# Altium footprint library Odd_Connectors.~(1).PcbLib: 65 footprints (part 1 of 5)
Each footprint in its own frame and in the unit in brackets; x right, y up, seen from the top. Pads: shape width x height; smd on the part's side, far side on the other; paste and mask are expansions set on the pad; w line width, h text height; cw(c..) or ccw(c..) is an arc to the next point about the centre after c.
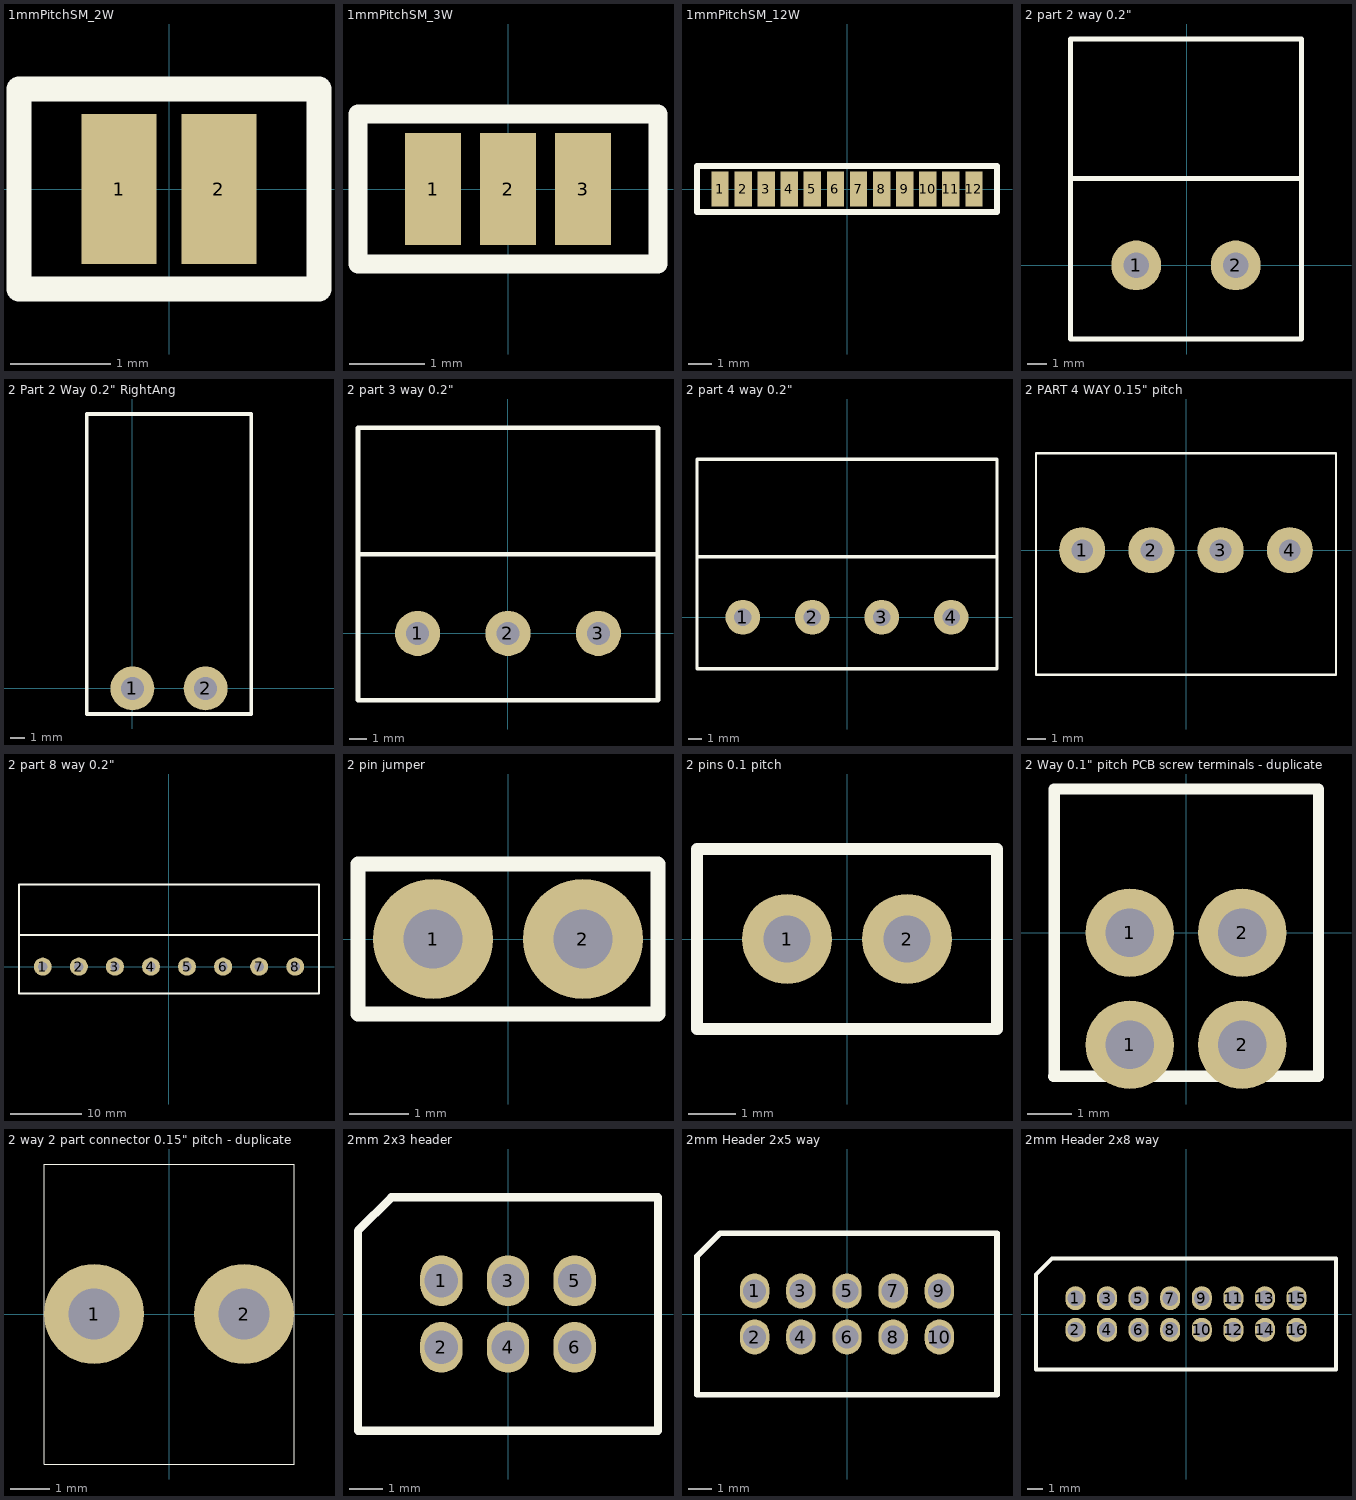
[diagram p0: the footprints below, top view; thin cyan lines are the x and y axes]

## 1mmPitchSM_2W [mm]
pads (2):
  rect 0.75x1.5 smd: 1(-0.5,0) 2(0.5,0)
Top Overlay:
  lines w0.254: -1.5,-1 -1.5,1 1.5,1 1.5,-1 -1.5,-1

## 1mmPitchSM_3W [mm]
pads (3):
  rect 0.75x1.5 smd: 1(-1,0) 2(0,0) 3(1,0)
Top Overlay:
  lines w0.254: -2,-1 -2,1 2,1 2,-1 -2,-1

## 1mmPitchSM_12W [mm]
pads (12):
  rect 0.75x1.5 smd: 1(-5.5,0) 2(-4.5,0) 3(-3.5,0) 4(-2.5,0) 5(-1.5,0) 6(-0.5,0) 7(0.5,0) 8(1.5,0) 9(2.5,0) 10(3.5,0) 11(4.5,0) 12(5.5,0)
Top Overlay:
  lines w0.254: -6.5,-1 6.5,-1 6.5,1 -6.5,1 -6.5,-1

## 2 part 2 way 0.2" [mm] "Two part connector (2 way) with plug shown"
height 12
pads (2):
  round 2.54 hole 1.3: 1(-2.58,0) 2(2.5,0)
Top Overlay:
  lines w0.254: -5.933,4.445 5.853,4.445 ; -5.933,-3.759 -5.933,11.557 5.853,11.557 5.853,-3.759 -5.933,-3.759

## 2 Part 2 Way 0.2" RightAng [mil] "2 part connector right angle 0.2\" pitch 2 way"
height 590.55
pads (2):
  round 120 hole 62.2: 1(0,0) 2(200,0)
Top Overlay:
  lines w10: -125,-70 325,-70 325,750 -125,750 -125,-70

## 2 part 3 way 0.2" [mm] "Two part connector (3 way) with plug shown"
height 12
pads (3):
  round 2.54 hole 1.3: 1(-5.08,0) 2(0,0) 3(5.08,0)
Top Overlay:
  lines w0.254: -8.433,4.445 8.433,4.445 ; -8.433,-3.759 -8.433,11.557 8.433,11.557 8.433,-3.759 -8.433,-3.759

## 2 part 4 way 0.2" [mm] "Two part connector (4 way) with plug shown"
height 12
pads (4):
  round 2.54 hole 1.3: 1(-7.62,0) 2(-2.54,0) 3(2.54,0) 4(7.62,0)
Top Overlay:
  lines w0.254: -10.973,4.445 10.973,4.445 ; -10.973,-3.759 10.973,-3.759 10.973,11.557 -10.973,11.557 -10.973,-3.759

## 2 PART 4 WAY 0.15" pitch [mm]
height 20
pads (4):
  round 2.54 hole 1.2: 1(-5.715,0) 2(-1.905,0) 3(1.905,0) 4(5.715,0)
Top Overlay:
  lines w0.127: 8.255,-1.905 8.255,-6.35 ; 8.255,-6.35 8.255,-6.858 -8.255,-6.858 -8.255,5.334 8.255,5.334 8.255,-6.35

## 2 part 8 way 0.2" [mm] "Two part connector (8 way) with plug shown"
height 12
pads (8):
  round 2.54 hole 1.3: 1(-17.78,0) 2(-12.7,0) 3(-7.62,0) 4(-2.54,0) 5(2.54,0) 6(7.62,0) 7(12.7,0) 8(17.78,0)
Top Overlay:
  lines w0.254: -21.133,4.445 21.133,4.445 ; -21.133,-3.759 -21.133,11.557 21.133,11.557 21.133,-3.759 -21.133,-3.759

## 2 pin jumper [mil] "2 pin jumper on 0.1\" pitch"
height 984.25
pads (2):
  round 80 hole 39.37: 1(-50,0) 2(50,0)
Top Overlay:
  lines w10: -100,-50 100,-50 100,50 -100,50 -100,-50

## 2 pins 0.1 pitch [mm] "pin header"
height 12
pads (2):
  round 1.905 hole 1: 1(-1.27,0) 2(1.27,0)
Top Overlay:
  lines w0.254: -3.175,-1.905 3.175,-1.905 3.175,1.905 -3.175,1.905 -3.175,-1.905

## 2 Way 0.1" pitch PCB screw terminals - duplicate [mm]
height 8.5
pads (4):
  round 2 hole 1.1: 1(-1.27,-2.54) 1(-1.27,0) 2(1.27,-2.54) 2(1.27,0)
Top Overlay:
  lines w0.254: -3,-3.25 3,-3.25 3,3.25 -2.98,3.25 -2.98,-3.25

## 2 way 2 part connector 0.15" pitch - duplicate [mm] "2 way connector or terminal block - 0.15\" pitch"
height 10.16
pads (2):
  round 2.54 hole 1.3 unplated: 1(-1.905,0) 2(1.905,0)
Top Overlay:
  lines w0.025: -3.175,-3.81 -3.175,3.81 3.175,3.81 3.175,-3.81 -3.175,-3.81

## 2mm 2x3 header [mm]
pads (6):
  oval 1.27x1.524 / inner round 1.524 / far side round 1.524 hole 1: 1(-2,1) 2(-2,-1) 3(0,1) 4(0,-1) 5(2,1) 6(2,-1)
Top Overlay:
  lines w0.254: -4.5,-3.5 4.5,-3.5 4.5,3.5 -3.5,3.5 -4.5,2.5 -4.5,-3.5

## 2mm Header 2x5 way [mm] "Milligrid 87831 etc"
pads (10):
  oval 1.27x1.524 / inner round 1.524 / far side round 1.524 hole 1: 1(-4,1) 2(-4,-1) 3(-2,1) 4(-2,-1) 5(0,1) 6(0,-1) 7(2,1) 8(2,-1) 9(4,1) 10(4,-1)
Top Overlay:
  lines w0.254: -6.5,-3.5 6.5,-3.5 6.5,3.5 -5.5,3.5 -6.5,2.5 -6.5,-3.5

## 2mm Header 2x8 way [mm] "Milligrid 87831 etc"
pads (16):
  oval 1.27x1.524 / inner round 1.524 / far side round 1.524 hole 1: 1(-7,1) 2(-7,-1) 3(-5,1) 4(-5,-1) 5(-3,1) 6(-3,-1) 7(-1,1) 8(-1,-1) 9(1,1) 10(1,-1) 11(3,1) 12(3,-1) 13(5,1) 14(5,-1) 15(7,1) 16(7,-1)
Top Overlay:
  lines w0.254: -9.5,-3.5 9.5,-3.5 9.5,3.5 -8.5,3.5 -9.5,2.5 -9.5,-3.5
